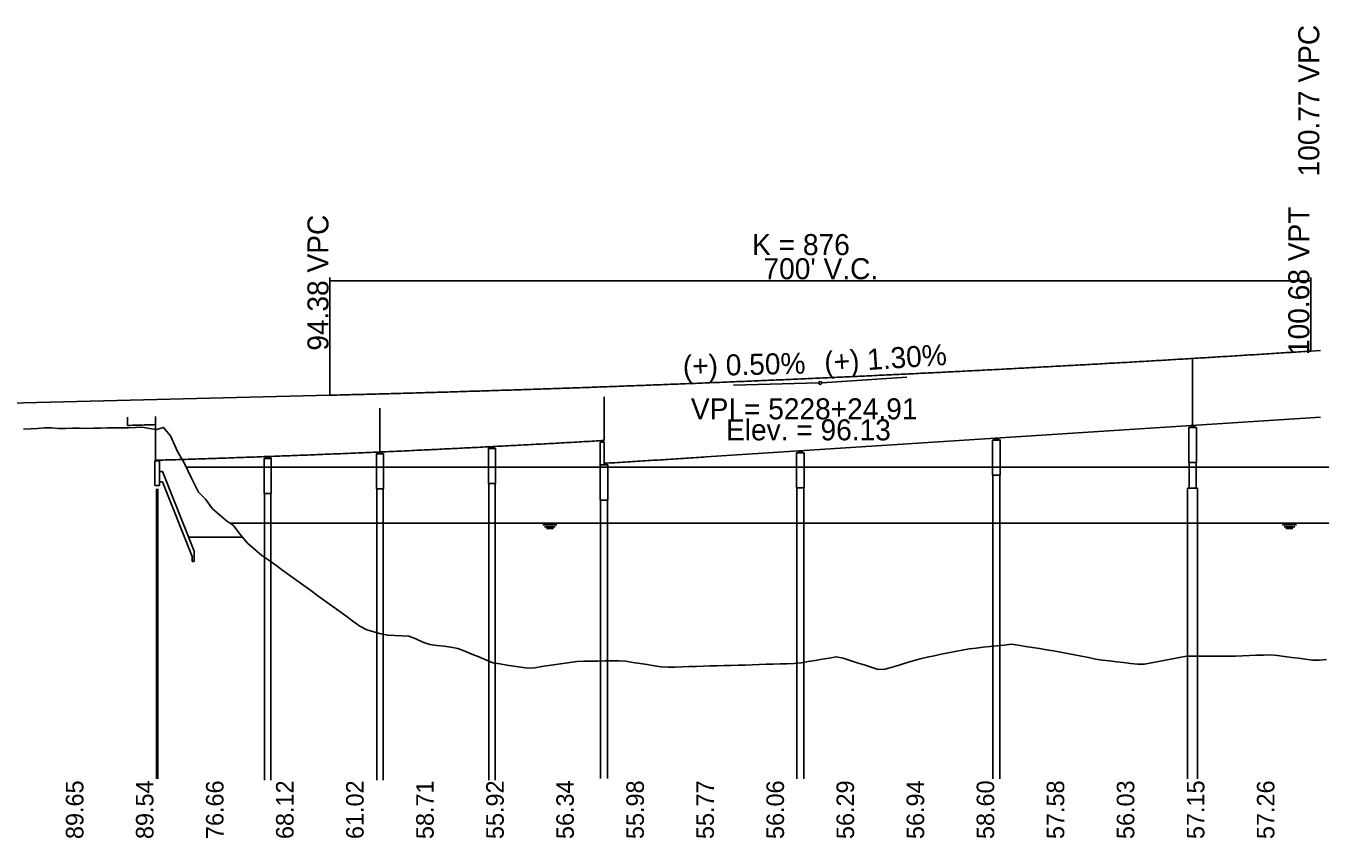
# Model space of a CAD drawing. Extents: x 2121671 to 2169879, y 557274 to 599957.
# Drawn here: x 2151826 to 2152750, y 595763 to 596343 of the extents above; entities that cross this region are included whole.
import ezdxf

# ---------------------------------------------------------------- set-up
doc = ezdxf.new("R2010")
doc.units = 0
for name, color, linetype in [('BR_CONCRETE', 7, 'Continuous'), ('BR_DETAILS', 7, 'Continuous'), ('BR_PRESTRESSED BEAM', 7, 'Continuous'), ('BR_STRUCTURAL STEEL', 7, 'Continuous'), ('RD_DDB_GradeTX', 7, 'Continuous'), ('RD_DDB_Profile_Elev', 7, 'Continuous'), ('RD_DDB_Profile_EX', 7, 'Continuous'), ('RD_DDB_Profile_Lbl', 7, 'Continuous'), ('RD_DDB_Profile_PR', 7, 'Continuous'), ('RD_DDB_StripGrade', 7, 'Continuous'), ('RD_DDB_VCLbl', 7, 'Continuous')]:
    doc.layers.add(name, color=color, linetype=linetype)

msp = doc.modelspace()

# ---------------------------------------------------------------- linework, layer by layer
at = {"layer": 'BR_CONCRETE'}
for p, q in [((2151898.82, 596063.63), (2151898.82, 596057.79)), ((2152236.07, 596029.6), (2152236.07, 596045.79)), ((2152236.07, 596045.79), (2152238.82, 596045.79)), ((2152238.82, 596045.79), (2152238.82, 596029.6)), ((2152656.32, 596031.43), (2152656.32, 596013.07)), ((2152661.32, 596031.43), (2152661.32, 596013.07)), ((2152516.32, 596022.33), (2152516.32, 596013.07)), ((2152521.32, 596022.33), (2152521.32, 596013.07)), ((2152076.57, 596012.55), (2152076.57, 595804.68)), ((2152081.07, 596012.55), (2152081.07, 595804.68)), ((2152156.57, 596016.35), (2152156.57, 595804.69)), ((2152161.07, 596016.35), (2152161.07, 595804.69)), ((2152376.32, 596013.23), (2152376.32, 596013.07)), ((2152376.32, 596013.07), (2152376.32, 595805.78)), ((2152381.32, 596013.23), (2152381.32, 596013.07)), ((2152381.32, 596013.07), (2152381.32, 595805.78)), ((2152516.32, 596013.07), (2152516.32, 595805.78)), ((2152521.32, 596013.07), (2152521.32, 595805.78)), ((2152655.32, 596013.07), (2152655.32, 595805.78)), ((2152662.32, 596013.07), (2152662.32, 595805.78)), ((2151996.57, 596009.32), (2151996.57, 595804.67)), ((2152001.07, 596009.32), (2152001.07, 595804.67)), ((2152236.32, 596004.6), (2152236.32, 595805.88)), ((2152241.32, 596004.6), (2152241.32, 595805.88))]:
    msp.add_line(p, q, dxfattribs=at)
for points in [[(2152656.07, 596031.43), (2152661.57, 596031.43), (2152661.57, 596056.43), (2152656.07, 596056.43)], [(2152156.32, 596016.35), (2152161.32, 596016.35), (2152161.32, 596041.35), (2152156.32, 596041.35)], [(2152516.07, 596022.33), (2152521.57, 596022.33), (2152521.57, 596047.33), (2152516.07, 596047.33)], [(2151918.16, 596015.05), (2151921.66, 596015.05), (2151921.66, 596032.55), (2151918.16, 596032.55)], [(2151996.32, 596009.32), (2152001.32, 596009.32), (2152001.32, 596034.32), (2151996.32, 596034.32)], [(2152076.32, 596012.55), (2152081.32, 596012.55), (2152081.32, 596037.55), (2152076.32, 596037.55)], [(2152236.07, 596004.6), (2152241.57, 596004.6), (2152241.57, 596029.6), (2152236.07, 596029.6)], [(2152376.07, 596013.23), (2152381.57, 596013.23), (2152381.57, 596038.23), (2152376.07, 596038.23)]]:
    msp.add_lwpolyline(points, close=True, dxfattribs=at)
msp.add_spline([(2151898.82, 596057.79), (2151905.74, 596057.99), (2151918.82, 596058.37)], degree=3, dxfattribs=at)
at = {"layer": 'BR_DETAILS'}
for p, q in [((2151921.66, 596025.01), (2151923.66, 596025.01)), ((2151946.42, 595968.12), (2151923.66, 596025.01)), ((2151921.66, 596017.51), (2151923.66, 596017.51)), ((2151944.92, 595964.37), (2151923.66, 596017.51)), ((2151942.42, 595978.12), (2151980.88, 595978.12)), ((2151946.42, 595968.12), (2151946.42, 595960.62)), ((2151944.92, 595960.62), (2151944.92, 595964.37)), ((2151946.42, 595960.62), (2151944.92, 595960.62))]:
    msp.add_line(p, q, dxfattribs=at)
for points in [[(2152657.32, 596057.68), (2152658.32, 596057.68), (2152658.32, 596056.43), (2152657.32, 596056.43)], [(2152659.32, 596057.68), (2152660.32, 596057.68), (2152660.32, 596056.43), (2152659.32, 596056.43)], [(2152517.32, 596048.58), (2152518.32, 596048.58), (2152518.32, 596047.33), (2152517.32, 596047.33)], [(2152519.32, 596048.58), (2152520.32, 596048.58), (2152520.32, 596047.33), (2152519.32, 596047.33)], [(2152077.32, 596038.8), (2152078.32, 596038.8), (2152078.32, 596037.55), (2152077.32, 596037.55)], [(2152079.32, 596038.8), (2152080.32, 596038.8), (2152080.32, 596037.55), (2152079.32, 596037.55)], [(2152157.32, 596042.6), (2152158.32, 596042.6), (2152158.32, 596041.35), (2152157.32, 596041.35)], [(2152159.32, 596042.6), (2152160.32, 596042.6), (2152160.32, 596041.35), (2152159.32, 596041.35)], [(2152237.32, 596047.04), (2152238.32, 596047.04), (2152238.32, 596045.79), (2152237.32, 596045.79)], [(2152377.32, 596039.48), (2152378.32, 596039.48), (2152378.32, 596038.23), (2152377.32, 596038.23)], [(2152379.32, 596039.48), (2152380.32, 596039.48), (2152380.32, 596038.23), (2152379.32, 596038.23)], [(2151919.32, 596032.97), (2151920.49, 596032.97), (2151920.49, 596032.55), (2151919.32, 596032.55)], [(2151997.32, 596035.57), (2151998.32, 596035.57), (2151998.32, 596034.32), (2151997.32, 596034.32)], [(2151999.32, 596035.57), (2152000.32, 596035.57), (2152000.32, 596034.32), (2151999.32, 596034.32)], [(2152239.32, 596030.85), (2152240.32, 596030.85), (2152240.32, 596029.6), (2152239.32, 596029.6)]]:
    msp.add_lwpolyline(points, close=True, dxfattribs=at)
at = {"layer": 'BR_PRESTRESSED BEAM'}
for p, q in [((2152658.82, 596057.78), (2152658.82, 596105.28)), ((2152238.82, 596047.07), (2152238.82, 596078.32)), ((2152078.82, 596038.86), (2152078.82, 596070.11)), ((2151918.82, 596064.2), (2151918.82, 596032.95)), ((2152311.74, 596035.32), (2152750.24, 596063.82)), ((2152655.32, 596013.07), (2152662.32, 596013.07))]:
    msp.add_line(p, q, dxfattribs=at)
for points in [[(2151918.82, 596032.95), (2151920.24, 596032.99), (2151934.74, 596033.44), (2151949.24, 596033.9), (2151963.74, 596034.38), (2151978.24, 596034.88), (2151992.74, 596035.4), (2152007.24, 596035.94), (2152021.74, 596036.49), (2152036.24, 596037.07), (2152050.74, 596037.66), (2152065.24, 596038.27), (2152079.74, 596038.9), (2152094.24, 596039.55), (2152108.74, 596040.22), (2152123.24, 596040.91), (2152137.74, 596041.62), (2152152.24, 596042.34), (2152166.74, 596043.09), (2152181.24, 596043.85), (2152195.74, 596044.63), (2152210.24, 596045.44), (2152224.74, 596046.26), (2152238.82, 596047.07)], [(2152238.82, 596030.82), (2152239.24, 596030.84), (2152253.74, 596031.7), (2152268.24, 596032.58), (2152282.74, 596033.47), (2152297.24, 596034.39), (2152311.74, 596035.32)]]:
    msp.add_spline(points, degree=3, dxfattribs=at)
at = {"layer": 'BR_STRUCTURAL STEEL'}
for p, q in [((2151919.32, 596012.51), (2151919.32, 595805.58)), ((2151920.49, 596012.51), (2151920.49, 595805.58))]:
    msp.add_line(p, q, dxfattribs=at)
at = {"layer": 'RD_DDB_GradeTX'}
for p, q in [((2152331.17, 596086.57), (2152392.16, 596088.09)), ((2152455.02, 596092.14), (2152394.15, 596088.18))]:
    msp.add_line(p, q, dxfattribs=at)
msp.add_circle((2152393.15, 596088.12), 1, dxfattribs=at)
at = {"layer": 'RD_DDB_Profile_Elev'}
for p, q in [((2151940.69, 596028.07), (2155629.71, 596028.07)), ((2151971.97, 595988.07), (2156334.94, 595988.07)), ((2152195.16, 595986.82), (2152205.16, 595986.82)), ((2152196.41, 595985.57), (2152203.91, 595985.57)), ((2152197.66, 595984.32), (2152202.66, 595984.32)), ((2152723, 595986.82), (2152733, 595986.82)), ((2152724.25, 595985.57), (2152731.75, 595985.57)), ((2152725.5, 595984.32), (2152730.5, 595984.32))]:
    msp.add_line(p, q, dxfattribs=at)
at = {"layer": 'RD_DDB_Profile_EX'}
for points in [[(2151824.48, 596055.23), (2151829.48, 596055.31), (2151834.48, 596055.57), (2151839.48, 596055.98), (2151844.48, 596055.98), (2151849.48, 596055.53), (2151854.48, 596055.69), (2151859.48, 596055.83), (2151864.48, 596055.79), (2151869.48, 596055.67), (2151874.48, 596055.78), (2151879.48, 596055.97), (2151884.48, 596056.16), (2151889.48, 596055.98), (2151894.48, 596056.08), (2151899.48, 596056.01), (2151904.48, 596056.23), (2151909.48, 596056.55), (2151914.48, 596055.74), (2151919.48, 596054.96), (2151924.48, 596056.45), (2151929.48, 596050.33), (2151934.48, 596039.19), (2151939.48, 596030.54), (2151944.48, 596020.27), (2151949.48, 596010.09), (2151954.48, 596005.12), (2151959.48, 595998.24), (2151964.48, 595993.98), (2151969.48, 595989.72), (2151974.48, 595986.4), (2151979.48, 595979.81), (2151984.48, 595973.75), (2151989.48, 595969.33), (2151994.48, 595964.99), (2151999.48, 595961.56), (2152004.48, 595958.03), (2152009.48, 595954.42), (2152014.48, 595950.8), (2152019.48, 595947.18), (2152024.48, 595943.57), (2152029.48, 595939.95), (2152034.48, 595936.33), (2152039.48, 595932.72), (2152044.48, 595929.1), (2152049.48, 595925.48), (2152054.48, 595921.87), (2152059.48, 595918.25), (2152064.48, 595914.63), (2152069.48, 595911.89), (2152074.48, 595910.47), (2152079.48, 595909.05), (2152084.48, 595908.12), (2152089.48, 595907.89), (2152094.48, 595907.67), (2152099.48, 595907.44), (2152104.48, 595905.51), (2152109.48, 595903.15), (2152114.48, 595901.46), (2152119.48, 595900.87), (2152124.48, 595900.28), (2152129.48, 595899.69), (2152134.48, 595898.75), (2152139.48, 595896.73), (2152144.48, 595894.72), (2152149.48, 595892.7), (2152154.48, 595890.68), (2152159.48, 595888.34), (2152164.48, 595887.61), (2152169.48, 595886.88), (2152174.48, 595886.16), (2152179.48, 595885.43), (2152184.48, 595884.7), (2152189.48, 595884.95), (2152194.48, 595885.72)], [(2152194.48, 595885.72), (2152199.48, 595886.45), (2152204.48, 595887.17), (2152209.48, 595887.9), (2152214.48, 595888.63), (2152219.48, 595889.35), (2152224.48, 595889.55), (2152229.48, 595889.62), (2152234.48, 595889.69), (2152239.48, 595889.76), (2152244.48, 595889.83), (2152249.48, 595889.85), (2152254.48, 595889.53), (2152259.48, 595888.74), (2152264.48, 595887.96), (2152269.48, 595887.18), (2152274.48, 595886.39), (2152279.48, 595885.61), (2152284.48, 595885.25), (2152289.48, 595885.4), (2152294.48, 595885.56), (2152299.48, 595885.71), (2152304.48, 595885.86), (2152309.48, 595886.01), (2152314.48, 595886.24), (2152319.48, 595886.34), (2152324.48, 595886.45), (2152329.48, 595886.55), (2152334.48, 595886.65), (2152339.48, 595886.75), (2152344.48, 595887.11), (2152349.48, 595887.26), (2152354.48, 595887.4), (2152359.48, 595887.53), (2152364.48, 595887.67), (2152369.48, 595887.81), (2152374.48, 595887.85), (2152379.48, 595888.5), (2152384.48, 595889.33), (2152389.48, 595890.16), (2152394.48, 595890.99), (2152399.48, 595891.83), (2152404.48, 595892.66), (2152409.48, 595891.76), (2152414.48, 595890.14), (2152419.48, 595888.53), (2152424.48, 595886.91), (2152429.48, 595885.3), (2152434.48, 595883.68), (2152439.48, 595883.95), (2152444.48, 595885.42), (2152449.48, 595886.88), (2152454.48, 595888.35), (2152459.48, 595889.81), (2152464.48, 595891.28), (2152469.48, 595892.44), (2152474.48, 595893.47), (2152479.48, 595894.5), (2152484.48, 595895.53), (2152489.48, 595896.55), (2152494.48, 595897.58), (2152499.48, 595898.49), (2152504.48, 595899.01), (2152509.48, 595899.54), (2152514.48, 595900.06), (2152519.48, 595900.58), (2152524.48, 595901.1), (2152529.48, 595901.63), (2152534.48, 595900.95), (2152539.48, 595900.17), (2152544.48, 595899.38), (2152549.48, 595898.6), (2152554.48, 595897.81), (2152559.48, 595897.03), (2152564.48, 595896.1), (2152569.48, 595895.1), (2152574.48, 595894.11), (2152579.48, 595893.12), (2152584.48, 595892.13), (2152589.48, 595891.13), (2152594.48, 595890.43), (2152599.48, 595889.84), (2152604.48, 595889.24), (2152609.48, 595888.64), (2152614.48, 595888.04), (2152619.48, 595887.45), (2152624.48, 595887.51), (2152629.48, 595888.46), (2152634.48, 595889.41), (2152639.48, 595890.37), (2152644.48, 595891.32), (2152649.48, 595892.27), (2152654.48, 595893.14), (2152659.48, 595893.17), (2152664.48, 595893.21), (2152669.48, 595893.24), (2152674.48, 595893.27), (2152679.48, 595893.3), (2152684.48, 595893.3), (2152689.48, 595893.28), (2152694.48, 595893.46)], [(2152694.48, 595893.46), (2152699.48, 595893.63), (2152704.48, 595893.81), (2152709.48, 595893.98), (2152714.48, 595894.16), (2152719.48, 595893.66), (2152724.48, 595893), (2152729.48, 595892.34), (2152734.48, 595891.68), (2152739.48, 595891.02), (2152744.48, 595890.36), (2152749.48, 595890.41), (2152754.48, 595890.85)]]:
    msp.add_lwpolyline(points, dxfattribs=at)
at = {"layer": 'RD_DDB_Profile_PR'}
for p, q in [((2152743.15, 596110.87), (2152750.24, 596111.33)), ((2151239.77, 596059.26), (2152043.15, 596079.36))]:
    msp.add_line(p, q, dxfattribs=at)
msp.add_spline([(2152043.15, 596079.36), (2152057.15, 596079.72), (2152071.15, 596080.08), (2152085.15, 596080.46), (2152099.15, 596080.85), (2152113.15, 596081.25), (2152127.15, 596081.66), (2152141.15, 596082.09), (2152155.15, 596082.52), (2152169.15, 596082.97), (2152183.15, 596083.42), (2152197.15, 596083.89), (2152211.15, 596084.37), (2152225.15, 596084.86), (2152239.15, 596085.36), (2152253.15, 596085.88), (2152267.15, 596086.4), (2152281.15, 596086.93), (2152295.15, 596087.48), (2152309.15, 596088.04), (2152323.15, 596088.61), (2152337.15, 596089.19), (2152351.15, 596089.78), (2152365.15, 596090.38), (2152379.15, 596090.99), (2152393.15, 596091.62), (2152407.15, 596092.25), (2152421.15, 596092.9), (2152435.15, 596093.56), (2152449.15, 596094.23), (2152463.15, 596094.91), (2152477.15, 596095.6), (2152491.15, 596096.3), (2152505.15, 596097.02), (2152519.15, 596097.74), (2152533.15, 596098.48), (2152547.15, 596099.23), (2152561.15, 596099.98), (2152575.15, 596100.75), (2152589.15, 596101.54), (2152603.15, 596102.33), (2152617.15, 596103.13), (2152631.15, 596103.95), (2152645.15, 596104.77), (2152659.15, 596105.61), (2152673.15, 596106.46), (2152687.15, 596107.32), (2152701.15, 596108.19), (2152715.15, 596109.07), (2152729.15, 596109.96), (2152743.15, 596110.87)], degree=3, dxfattribs=at)
at = {"layer": 'RD_DDB_VCLbl'}
for p, q in [((2152043.15, 596163.37), (2152043.15, 596079.36)), ((2152043.15, 596160.87), (2152743.15, 596160.87)), ((2152743.15, 596163.37), (2152743.15, 596110.87))]:
    msp.add_line(p, q, dxfattribs=at)

# ---------------------------------------------------------------- texts
at = {"layer": 'RD_DDB_GradeTX'}
for s, rotation, p in [('(+) 1.30%', 3.71869, (2152396.46, 596095.3)), ('(+) 0.50%', 1.43336, (2152295.24, 596092.63))]:
    msp.add_text(s, height=15, rotation=rotation, dxfattribs=at).set_placement(p)
at = {"layer": 'RD_DDB_Profile_Lbl'}
for s, p in [('VPI = 5228+24.91', (2152300.79, 596062.16)), ('Elev. = 96.13', (2152325.86, 596047.16))]:
    msp.add_text(s, height=15, dxfattribs=at).set_placement(p)
at = {"layer": 'RD_DDB_StripGrade'}
for s, height, p in [('100.77 VPC', 15, (2152749.24, 596235.47)), ('94.38 VPC', 15, (2152042.15, 596111.14)), ('100.68 VPT', 15, (2152742.15, 596108.04)), ('89.65', 12.5, (2151867.24, 595762.7)), ('89.54', 12.5, (2151917.24, 595762.7)), ('76.66', 12.5, (2151967.24, 595762.7)), ('68.12', 12.5, (2152017.24, 595762.7)), ('61.02', 12.5, (2152067.24, 595762.7)), ('58.71', 12.5, (2152117.24, 595762.7)), ('55.92', 12.5, (2152167.24, 595762.7)), ('56.34', 12.5, (2152217.24, 595762.7)), ('55.98', 12.5, (2152267.24, 595762.7)), ('55.77', 12.5, (2152317.24, 595762.7)), ('56.06', 12.5, (2152367.24, 595762.7)), ('56.29', 12.5, (2152417.24, 595762.7)), ('56.94', 12.5, (2152467.24, 595762.7)), ('58.60', 12.5, (2152517.24, 595762.7)), ('57.58', 12.5, (2152567.24, 595762.7)), ('56.03', 12.5, (2152617.24, 595762.7)), ('57.15', 12.5, (2152667.24, 595762.7)), ('57.26', 12.5, (2152717.24, 595762.7))]:
    msp.add_text(s, height=height, rotation=90, dxfattribs=at).set_placement(p)
at = {"layer": 'RD_DDB_VCLbl'}
for s, p in [('K = 876', (2152344.51, 596179.33)), ("700' V.C.", (2152352.6, 596162.12))]:
    msp.add_text(s, height=15, dxfattribs=at).set_placement(p)

doc.saveas('drawing.dxf')
